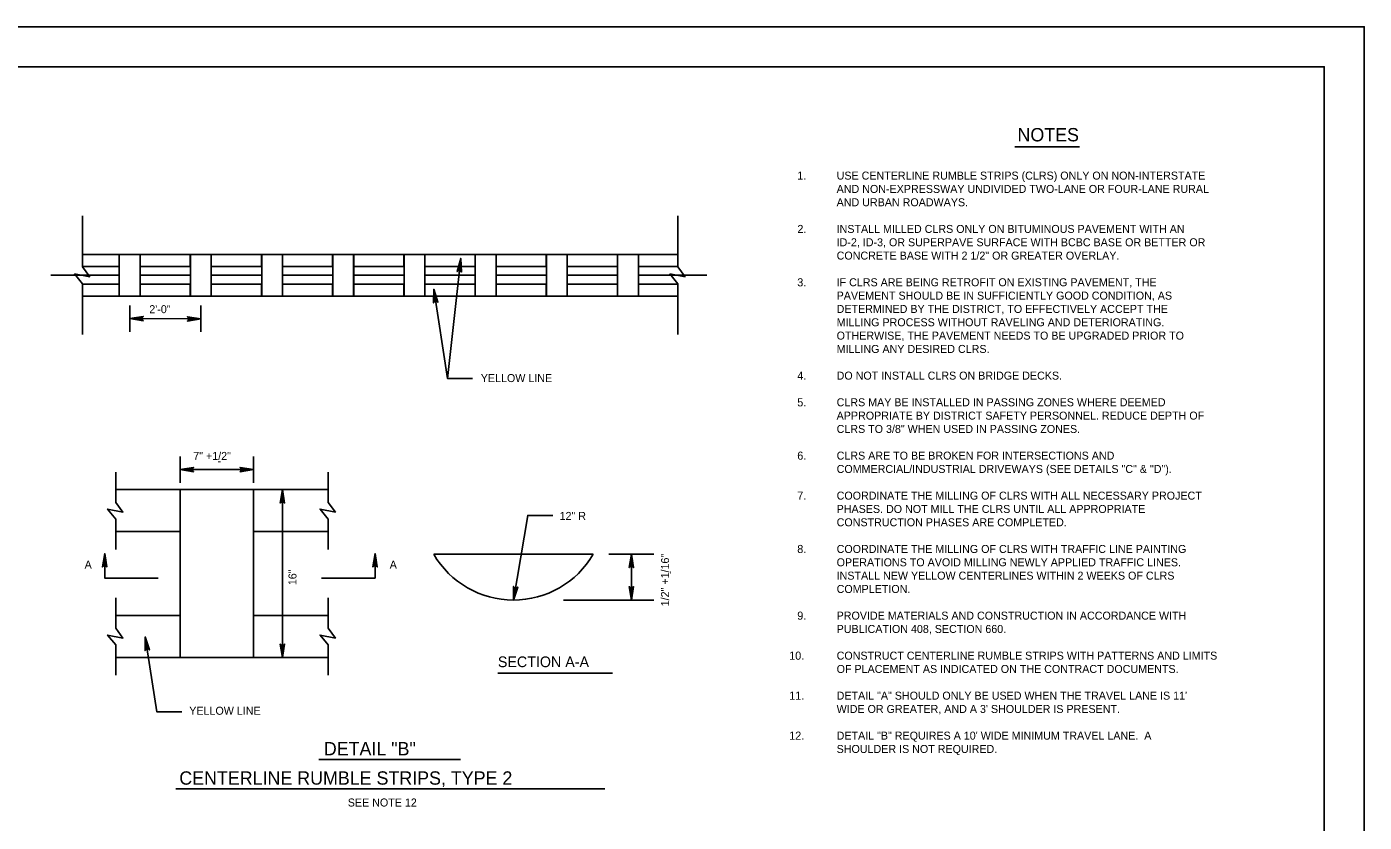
# Model space of a CAD drawing. Extents: x 632008 to 634206, y 294231 to 297795.
# Drawn here: x 632348 to 632849, y 297496 to 297795 of the extents above; entities that cross this region are included whole.
import ezdxf

# ---------------------------------------------------------------- set-up
doc = ezdxf.new("R2010")
doc.units = 0
for name, color, linetype in [('1', 7, 'Continuous'), ('Level 2', 7, 'Continuous'), ('PLT-BNDY', 7, 'Continuous')]:
    doc.layers.add(name, color=color, linetype=linetype)

msp = doc.modelspace()

# ---------------------------------------------------------------- linework, layer by layer
at = {"layer": '1'}
for p, q in [((632717.95, 297749.62), (632742.18, 297749.62)), ((632524.13, 297552.16), (632567.07, 297552.16)), ((632457.03, 297519.79), (632510.1, 297519.79)), ((632403.41, 297508.79), (632564.24, 297508.79))]:
    msp.add_line(p, q, dxfattribs=at)
msp.add_lwpolyline([(632833.86, 297215.62), (632833.86, 297779.62), (632047.86, 297779.62), (632047.86, 297215.62), (632833.86, 297215.62), (632833.86, 297241.98), (632633.86, 297241.98), (632633.86, 297306.66), (632833.86, 297306.66), (632833.86, 297335.62), (632633.86, 297335.62), (632633.86, 297215.62), (632712.66, 297215.62), (632712.66, 297241.98), (632712.66, 297215.62), (632789.66, 297215.62), (632789.66, 297241.98), (632789.66, 297229.66), (632833.86, 297229.66)], dxfattribs=at)
for points in [[(632368.44, 297709.21), (632382.23, 297709.21), (632382.23, 297704.76), (632368.44, 297704.76)], [(632390.02, 297709.21), (632408.84, 297709.21), (632408.84, 297704.76), (632390.02, 297704.76)], [(632416.71, 297709.21), (632435.53, 297709.21), (632435.53, 297704.76), (632416.71, 297704.76)], [(632443.39, 297709.21), (632462.21, 297709.21), (632462.21, 297704.76), (632443.39, 297704.76)], [(632470.07, 297709.21), (632488.89, 297709.21), (632488.89, 297704.76), (632470.07, 297704.76)], [(632496.77, 297709.21), (632515.59, 297709.21), (632515.59, 297704.76), (632496.77, 297704.76)], [(632523.45, 297709.21), (632542.28, 297709.21), (632542.28, 297704.76), (632523.45, 297704.76)], [(632550.13, 297709.21), (632568.96, 297709.21), (632568.96, 297704.76), (632550.13, 297704.76)], [(632576.81, 297709.21), (632591.64, 297709.21), (632591.64, 297704.76), (632576.81, 297704.76)], [(632368.44, 297698.09), (632382.23, 297698.09), (632382.23, 297693.64), (632368.44, 297693.64)], [(632390.02, 297698.09), (632408.84, 297698.09), (632408.84, 297693.64), (632390.02, 297693.64)], [(632416.71, 297698.09), (632435.53, 297698.09), (632435.53, 297693.64), (632416.71, 297693.64)], [(632443.39, 297698.09), (632462.21, 297698.09), (632462.21, 297693.64), (632443.39, 297693.64)], [(632470.07, 297698.09), (632488.89, 297698.09), (632488.89, 297693.64), (632470.07, 297693.64)], [(632496.77, 297698.09), (632515.59, 297698.09), (632515.59, 297693.64), (632496.77, 297693.64)], [(632523.45, 297698.09), (632542.28, 297698.09), (632542.28, 297693.64), (632523.45, 297693.64)], [(632550.13, 297698.09), (632568.96, 297698.09), (632568.96, 297693.64), (632550.13, 297693.64)], [(632576.81, 297698.09), (632591.63, 297698.09), (632591.63, 297693.64), (632576.81, 297693.64)], [(632405.04, 297621.04), (632380.89, 297621.04), (632380.89, 297616.27), (632383.63, 297612.61), (632377.87, 297613.73), (632380.89, 297610), (632380.89, 297605.3), (632405.04, 297605.3)], [(632432.58, 297621.04), (632460.52, 297621.04), (632460.52, 297616.27), (632463.27, 297612.61), (632457.51, 297613.73), (632460.52, 297610), (632460.52, 297605.3), (632432.58, 297605.3)], [(632405.04, 297573.83), (632380.89, 297573.83), (632380.89, 297569.06), (632383.63, 297565.4), (632377.87, 297566.52), (632380.89, 297562.8), (632380.89, 297558.09), (632405.04, 297558.09)], [(632432.58, 297573.83), (632460.52, 297573.83), (632460.52, 297569.06), (632463.27, 297565.4), (632457.51, 297566.52), (632460.52, 297562.8), (632460.52, 297558.09), (632432.58, 297558.09)]]:
    msp.add_lwpolyline(points, close=True, dxfattribs=at)
at = {"layer": 'Level 2'}
for p, q in [((632368.44, 297723.7), (632368.44, 297704.53)), ((632591.64, 297723.7), (632591.64, 297704.53)), ((632368.44, 297709.21), (632591.64, 297709.21)), ((632390.1, 297709.21), (632408.98, 297709.21)), ((632416.78, 297709.21), (632435.66, 297709.21)), ((632416.8, 297709.21), (632435.68, 297709.21)), ((632443.46, 297709.21), (632462.34, 297709.21)), ((632443.48, 297709.21), (632462.36, 297709.21)), ((632470.14, 297709.21), (632489.02, 297709.21)), ((632470.16, 297709.21), (632489.04, 297709.21)), ((632496.84, 297709.21), (632515.72, 297709.21)), ((632505.22, 297662.73), (632510.2, 297707.74)), ((632523.52, 297709.21), (632542.4, 297709.21)), ((632550.2, 297709.21), (632569.08, 297709.21)), ((632368.44, 297704.76), (632382.23, 297704.76)), ((632368.44, 297704.53), (632371.18, 297700.87)), ((632390.02, 297704.76), (632408.92, 297704.76)), ((632416.71, 297704.76), (632435.61, 297704.76)), ((632416.73, 297704.76), (632435.63, 297704.76)), ((632443.39, 297704.76), (632462.29, 297704.76)), ((632443.41, 297704.76), (632462.31, 297704.76)), ((632470.07, 297704.76), (632488.97, 297704.76)), ((632470.09, 297704.76), (632488.99, 297704.76)), ((632496.77, 297704.76), (632515.67, 297704.76)), ((632523.45, 297704.76), (632542.35, 297704.76)), ((632550.13, 297704.76), (632569.03, 297704.76)), ((632576.81, 297704.76), (632591.64, 297704.76)), ((632591.64, 297704.53), (632594.38, 297700.87)), ((632356.61, 297701.42), (632382.23, 297701.42)), ((632371.18, 297700.87), (632365.42, 297701.98)), ((632365.42, 297701.98), (632368.44, 297698.26)), ((632368.44, 297698.26), (632368.44, 297679.23)), ((632368.44, 297698.09), (632382.23, 297698.09)), ((632390.02, 297701.42), (632408.92, 297701.42)), ((632390.02, 297698.09), (632408.92, 297698.09)), ((632416.71, 297698.09), (632435.61, 297698.09)), ((632416.73, 297701.42), (632435.63, 297701.42)), ((632416.73, 297698.09), (632435.63, 297698.09)), ((632443.39, 297698.09), (632462.29, 297698.09)), ((632443.41, 297701.42), (632462.31, 297701.42)), ((632443.41, 297698.09), (632462.31, 297698.09)), ((632470.07, 297698.09), (632488.97, 297698.09)), ((632470.09, 297701.42), (632488.99, 297701.42)), ((632470.09, 297698.09), (632488.99, 297698.09)), ((632496.77, 297701.42), (632515.67, 297701.42)), ((632496.77, 297698.09), (632515.67, 297698.09)), ((632523.45, 297701.42), (632542.35, 297701.42)), ((632523.45, 297698.09), (632542.35, 297698.09)), ((632550.13, 297701.42), (632569.03, 297701.42)), ((632550.13, 297698.09), (632569.03, 297698.09)), ((632576.79, 297701.42), (632602.41, 297701.42)), ((632576.81, 297698.09), (632591.63, 297698.09)), ((632594.38, 297700.87), (632588.62, 297701.98)), ((632588.62, 297701.98), (632591.63, 297698.26)), ((632591.63, 297698.26), (632591.64, 297679.23)), ((632368.44, 297693.64), (632382.23, 297693.64)), ((632390.05, 297693.64), (632408.92, 297693.64)), ((632416.73, 297693.64), (632435.61, 297693.64)), ((632416.75, 297693.64), (632435.63, 297693.64)), ((632443.41, 297693.64), (632462.29, 297693.64)), ((632443.43, 297693.64), (632462.31, 297693.64)), ((632470.09, 297693.64), (632488.97, 297693.64)), ((632470.11, 297693.64), (632488.99, 297693.64)), ((632496.79, 297693.64), (632515.67, 297693.64)), ((632523.47, 297693.64), (632542.35, 297693.64)), ((632550.15, 297693.64), (632569.03, 297693.64)), ((632576.83, 297693.64), (632591.63, 297693.64)), ((632386.16, 297690.1), (632386.16, 297680.25)), ((632412.84, 297690.1), (632412.84, 297680.25)), ((632386.16, 297685.18), (632412.84, 297685.08)), ((632405.04, 297633.48), (632405.04, 297623.62)), ((632432.58, 297633.48), (632432.58, 297623.62)), ((632380.89, 297627.62), (632380.89, 297616.27)), ((632405.04, 297628.55), (632432.58, 297628.55)), ((632460.52, 297627.62), (632460.52, 297616.27)), ((632380.89, 297621.04), (632405.04, 297621.04)), ((632432.58, 297621.04), (632460.52, 297621.04)), ((632436.34, 297621.04), (632450.46, 297621.04)), ((632443.4, 297621.04), (632443.4, 297558.09)), ((632383.63, 297612.61), (632377.87, 297613.73)), ((632377.87, 297613.73), (632380.89, 297610)), ((632380.89, 297616.27), (632383.63, 297612.61)), ((632463.27, 297612.61), (632457.51, 297613.73)), ((632457.51, 297613.73), (632460.52, 297610)), ((632460.52, 297616.27), (632463.27, 297612.61)), ((632380.89, 297610), (632380.89, 297598.65)), ((632460.52, 297610), (632460.52, 297598.65)), ((632380.89, 297605.3), (632405.04, 297605.3)), ((632432.58, 297605.3), (632460.52, 297605.3)), ((632500.09, 297596.84), (632559.87, 297596.84)), ((632565.74, 297596.84), (632582.65, 297596.84)), ((632574.2, 297596.84), (632574.2, 297579.62)), ((632380.89, 297580.42), (632380.89, 297569.06)), ((632460.52, 297580.42), (632460.52, 297569.06)), ((632548.76, 297579.62), (632582.65, 297579.62)), ((632380.89, 297573.83), (632405.04, 297573.83)), ((632432.58, 297573.83), (632460.52, 297573.83)), ((632380.89, 297569.06), (632383.63, 297565.4)), ((632460.52, 297569.06), (632463.27, 297565.4)), ((632383.63, 297565.4), (632377.87, 297566.52)), ((632377.87, 297566.52), (632380.89, 297562.8)), ((632380.89, 297562.8), (632380.89, 297551.44)), ((632463.27, 297565.4), (632457.51, 297566.52)), ((632457.51, 297566.52), (632460.52, 297562.8)), ((632460.52, 297562.8), (632460.52, 297551.44)), ((632380.89, 297558.09), (632460.52, 297558.09))]:
    msp.add_line(p, q, dxfattribs=at)
for points in [[(632382.23, 297709.21), (632382.23, 297693.64), (632390.02, 297693.64), (632390.02, 297709.21)], [(632408.92, 297709.21), (632408.92, 297693.64), (632416.71, 297693.64), (632416.71, 297709.21)], [(632435.61, 297709.21), (632435.61, 297693.64), (632443.39, 297693.64), (632443.39, 297709.21)], [(632435.63, 297709.21), (632435.63, 297693.64), (632443.41, 297693.64), (632443.41, 297709.21)], [(632462.29, 297709.21), (632462.29, 297693.64), (632470.07, 297693.64), (632470.07, 297709.21)], [(632462.31, 297709.21), (632462.31, 297693.64), (632470.09, 297693.64), (632470.09, 297709.21)], [(632488.97, 297709.21), (632488.97, 297693.64), (632496.75, 297693.64), (632496.75, 297709.21)], [(632488.99, 297709.21), (632488.99, 297693.64), (632496.77, 297693.64), (632496.77, 297709.21)], [(632509.08, 297703.04), (632509.45, 297703.18), (632510.2, 297707.74), (632509.08, 297703.04), (632508.85, 297702.82), (632510.2, 297707.74), (632509.93, 297703.13), (632510.25, 297702.92), (632510.2, 297707.74), (632510.45, 297702.64), (632510.25, 297702.92)], [(632515.67, 297709.21), (632515.67, 297693.64), (632523.45, 297693.64), (632523.45, 297709.21)], [(632542.35, 297709.21), (632542.35, 297693.64), (632550.13, 297693.64), (632550.13, 297709.21)], [(632569.03, 297709.21), (632569.03, 297693.64), (632576.81, 297693.64), (632576.81, 297709.21)], [(632500.23, 297691.37), (632500.54, 297691.6), (632500.08, 297696.2), (632500.23, 297691.37), (632500.06, 297691.09), (632500.08, 297696.2), (632501.02, 297691.68), (632501.38, 297691.56), (632500.08, 297696.2), (632501.65, 297691.34), (632501.38, 297691.56)], [(632514.64, 297662.73), (632505.22, 297662.73), (632500.08, 297696.2)], [(632390.95, 297684.57), (632390.78, 297684.92), (632386.16, 297685.18), (632390.95, 297684.57), (632391.2, 297684.37), (632386.16, 297685.18), (632390.77, 297685.41), (632390.94, 297685.75), (632386.16, 297685.18), (632391.2, 297685.98), (632390.94, 297685.75)], [(632408.04, 297684.48), (632408.22, 297684.83), (632412.84, 297685.08), (632408.04, 297684.48), (632407.8, 297684.27), (632412.84, 297685.08), (632408.23, 297685.31), (632408.06, 297685.65), (632412.84, 297685.08), (632407.8, 297685.88), (632408.06, 297685.65)], [(632409.84, 297627.95), (632409.66, 297628.29), (632405.04, 297628.55), (632409.84, 297627.95), (632410.08, 297627.74), (632405.04, 297628.55), (632409.65, 297628.78), (632409.82, 297629.12), (632405.04, 297628.55), (632410.08, 297629.35), (632409.82, 297629.12)], [(632427.79, 297627.95), (632427.96, 297628.29), (632432.58, 297628.55), (632427.79, 297627.95), (632427.54, 297627.74), (632432.58, 297628.55), (632427.97, 297628.78), (632427.8, 297629.12), (632432.58, 297628.55), (632427.54, 297629.35), (632427.8, 297629.12)], [(632442.8, 297616.24), (632443.14, 297616.42), (632443.4, 297621.04), (632442.8, 297616.24), (632442.59, 297616), (632443.4, 297621.04), (632443.63, 297616.42), (632443.97, 297616.26), (632443.4, 297621.04), (632444.2, 297616), (632443.97, 297616.26)], [(632544.75, 297611.35), (632535.33, 297611.35), (632530.03, 297579.64)], [(632376.16, 297592.3), (632376.51, 297592.47), (632376.77, 297597.09), (632376.16, 297592.3), (632375.95, 297592.05), (632376.77, 297597.09), (632376.99, 297592.48), (632377.33, 297592.31), (632376.77, 297597.09), (632377.57, 297592.05), (632377.33, 297592.31)], [(632396.85, 297587.89), (632376.77, 297587.89), (632376.77, 297597.09)], [(632458.01, 297587.89), (632478.09, 297587.89), (632478.09, 297597.09)], [(632478.7, 297592.3), (632478.35, 297592.47), (632478.09, 297597.09), (632478.7, 297592.3), (632478.91, 297592.05), (632478.09, 297597.09), (632477.87, 297592.48), (632477.52, 297592.31), (632478.09, 297597.09), (632477.29, 297592.05), (632477.52, 297592.31)], [(632573.59, 297592.04), (632573.94, 297592.22), (632574.2, 297596.84), (632573.59, 297592.04), (632573.38, 297591.8), (632574.2, 297596.84), (632574.42, 297592.23), (632574.76, 297592.06), (632574.2, 297596.84), (632575, 297591.8), (632574.76, 297592.06)], [(632530.19, 297584.47), (632530.5, 297584.24), (632530.03, 297579.64), (632530.19, 297584.47), (632530.02, 297584.75), (632530.03, 297579.64), (632530.98, 297584.16), (632531.34, 297584.28), (632530.03, 297579.64), (632531.61, 297584.5), (632531.34, 297584.28)], [(632574.8, 297584.42), (632574.45, 297584.24), (632574.2, 297579.62), (632574.8, 297584.42), (632575, 297584.66), (632574.2, 297579.62), (632573.97, 297584.24), (632573.62, 297584.4), (632574.2, 297579.62), (632573.39, 297584.66), (632573.62, 297584.4)], [(632392.1, 297560.98), (632392.42, 297561.21), (632391.96, 297565.81), (632392.1, 297560.98), (632391.93, 297560.7), (632391.96, 297565.81), (632392.9, 297561.29), (632393.26, 297561.17), (632391.96, 297565.81), (632393.53, 297560.95), (632393.26, 297561.17)], [(632405.68, 297537.78), (632396.26, 297537.78), (632391.96, 297565.81)], [(632444, 297562.89), (632443.66, 297562.71), (632443.4, 297558.09), (632444, 297562.89), (632444.21, 297563.13), (632443.4, 297558.09), (632443.17, 297562.71), (632442.83, 297562.87), (632443.4, 297558.09), (632442.6, 297563.13), (632442.83, 297562.87)]]:
    msp.add_lwpolyline(points, dxfattribs=at)
msp.add_lwpolyline([(632405.04, 297558.09), (632432.58, 297558.09), (632432.58, 297621.04), (632405.04, 297621.04)], close=True, dxfattribs=at)
msp.add_arc((632529.98, 297614.18), 34.56, 210.1174, 329.8826, dxfattribs=at)
at = {"layer": 'PLT-BNDY'}
msp.add_lwpolyline([(632007.86, 297794.62), (632848.86, 297794.62), (632848.86, 297200.62), (632007.86, 297200.62)], close=True, dxfattribs=at)

# ---------------------------------------------------------------- texts
at = {"layer": '1'}
for s, height, p in [('NOTES', 5, (632718.9, 297751.64)), ('1.', 3.048, (632636.35, 297737.26)), ('USE CENTERLINE RUMBLE STRIPS (CLRS) ONLY ON NON-INTERSTATE ', 3, (632651.11, 297737.3)), ('AND NON-EXPRESSWAY UNDIVIDED TWO-LANE OR FOUR-LANE RURAL ', 3, (632651.11, 297732.3)), ('AND URBAN ROADWAYS.', 3, (632651.11, 297727.3)), ('2.', 3, (632636.41, 297717.3)), ('INSTALL MILLED CLRS ONLY ON BITUMINOUS PAVEMENT WITH AN ', 3, (632651.11, 297717.3)), ('ID-2, ID-3, OR SUPERPAVE SURFACE WITH BCBC BASE OR BETTER OR ', 3, (632651.11, 297712.3)), ('CONCRETE BASE WITH 2 1/2" OR GREATER OVERLAY.', 3, (632651.11, 297707.3)), ('3.', 3.048, (632636.35, 297697.26)), ('IF CLRS ARE BEING RETROFIT ON EXISTING PAVEMENT, THE ', 3, (632651.11, 297697.3)), ('PAVEMENT SHOULD BE IN SUFFICIENTLY GOOD CONDITION, AS ', 3, (632651.11, 297692.3)), ('DETERMINED BY THE DISTRICT, TO EFFECTIVELY ACCEPT THE ', 3, (632651.11, 297687.3)), ('MILLING PROCESS WITHOUT RAVELING AND DETERIORATING. ', 3, (632651.11, 297682.3)), ('OTHERWISE, THE PAVEMENT NEEDS TO BE UPGRADED PRIOR TO ', 3, (632651.11, 297677.3)), ('MILLING ANY DESIRED CLRS.', 3, (632651.11, 297672.3)), ('4.', 3.048, (632636.35, 297662.26)), ('DO NOT INSTALL CLRS ON BRIDGE DECKS.', 3, (632651.11, 297662.3)), ('5.', 3.048, (632636.35, 297652.26)), ('CLRS MAY BE INSTALLED IN PASSING ZONES WHERE DEEMED ', 3, (632651.11, 297652.3)), ('APPROPRIATE BY DISTRICT SAFETY PERSONNEL. REDUCE DEPTH OF ', 3, (632651.11, 297647.3)), ('CLRS TO 3/8" WHEN USED IN PASSING ZONES.', 3, (632651.11, 297642.3)), ('6.', 3.048, (632636.35, 297632.26)), ('CLRS ARE TO BE BROKEN FOR INTERSECTIONS AND ', 3, (632651.11, 297632.3)), ('COMMERCIAL/INDUSTRIAL DRIVEWAYS (SEE DETAILS "C" & "D").', 3, (632651.11, 297627.3)), ('7.', 3.048, (632636.35, 297617.26)), ('COORDINATE THE MILLING OF CLRS WITH ALL NECESSARY PROJECT ', 3, (632651.11, 297617.3)), ('PHASES. DO NOT MILL THE CLRS UNTIL ALL APPROPRIATE ', 3, (632651.11, 297612.3)), ('CONSTRUCTION PHASES ARE COMPLETED.', 3, (632651.11, 297607.3)), ('8.', 3.048, (632636.35, 297597.26)), ('COORDINATE THE MILLING OF CLRS WITH TRAFFIC LINE PAINTING ', 3, (632651.11, 297597.3)), ('OPERATIONS TO AVOID MILLING NEWLY APPLIED TRAFFIC LINES. ', 3, (632651.11, 297592.3)), ('INSTALL NEW YELLOW CENTERLINES WITHIN 2 WEEKS OF CLRS ', 3, (632651.11, 297587.3)), ('COMPLETION.', 3, (632651.11, 297582.3)), ('9.', 3.048, (632636.35, 297572.26)), ('PROVIDE MATERIALS AND CONSTRUCTION IN ACCORDANCE WITH ', 3, (632651.11, 297572.3)), ('PUBLICATION 408, SECTION 660.', 3, (632651.11, 297567.3)), ('10.', 3.048, (632633.31, 297557.26)), ('CONSTRUCT CENTERLINE RUMBLE STRIPS WITH PATTERNS AND LIMITS ', 3, (632651.11, 297557.3)), ('OF PLACEMENT AS INDICATED ON THE CONTRACT DOCUMENTS.', 3, (632651.11, 297552.3)), ('11.', 3.048, (632633.31, 297542.26)), ('DETAIL "A" SHOULD ONLY BE USED WHEN THE TRAVEL LANE IS 11\' ', 3, (632651.11, 297542.3)), ("WIDE OR GREATER, AND A 3' SHOULDER IS PRESENT.", 3, (632651.11, 297537.3)), ('12.', 3.048, (632633.31, 297527.26)), ('DETAIL "B" REQUIRES A 10\' WIDE MINIMUM TRAVEL LANE.  A ', 3, (632651.11, 297527.3)), ('SHOULDER IS NOT REQUIRED.', 3, (632651.11, 297522.3))]:
    msp.add_text(s, height=height, dxfattribs=at).set_placement(p)
at = {"layer": 'Level 2'}
for s, height, p in [('2\'-0"', 3, (632393.49, 297687.21)), ('YELLOW LINE', 3, (632517.73, 297661.38)), ('7" +1/2"', 3, (632409.97, 297632.18)), ('-', 3, (632419.12, 297630.27)), ('12" R', 3, (632547.27, 297609.68)), ('A', 3, (632369.25, 297591.42)), ('A', 3, (632483.6, 297591.42)), ('SECTION A-A', 4, (632524.13, 297554.48)), ('YELLOW LINE', 3, (632408.47, 297536.63)), ('DETAIL "B"', 5, (632458.91, 297521.41)), ('CENTERLINE RUMBLE STRIPS, TYPE 2', 5, (632404.73, 297510.41)), ('SEE NOTE 12', 3, (632467.89, 297502.22))]:
    msp.add_text(s, height=height, dxfattribs=at).set_placement(p)
for s, p in [('1/2" +1/16"', (632588.3, 297577.29)), ('16"', (632448.66, 297585.22)), ('-', (632590.07, 297589.3))]:
    msp.add_text(s, height=3, rotation=90, dxfattribs=at).set_placement(p)

doc.saveas('drawing.dxf')
